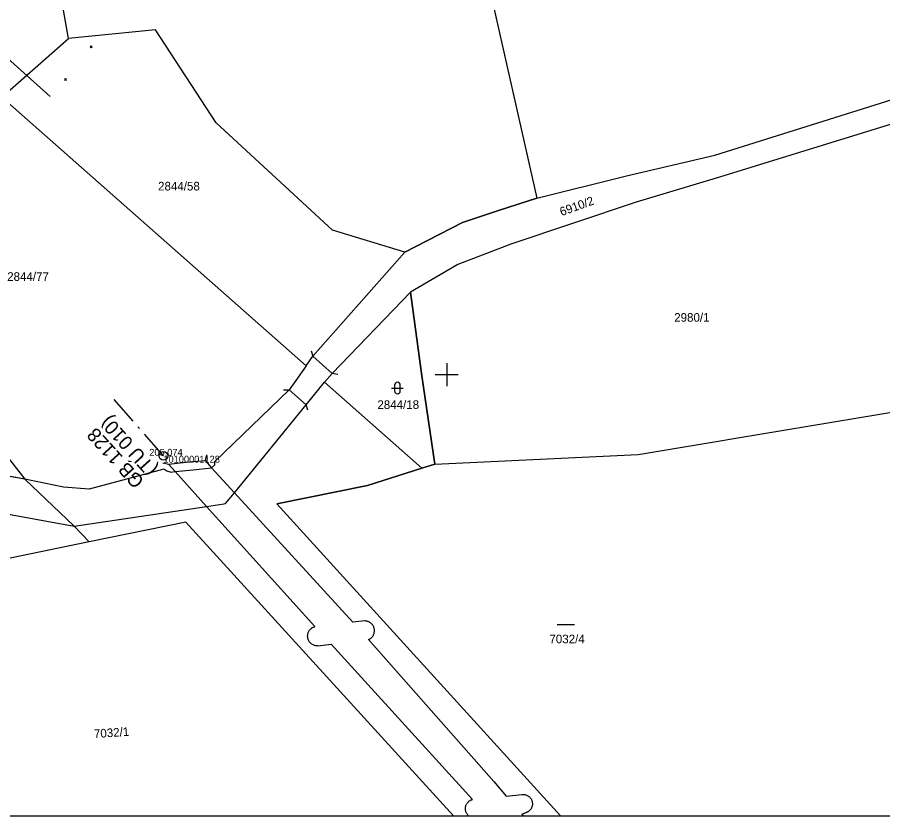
# Model space of a CAD drawing. Extents: x -800194 to -799078, y -1007177 to -1006597.
# Drawn here: x -799674.6 to -799524.3, y -1007176.6 to -1007037.9 of the extents above; entities that cross this region are included whole.
import ezdxf

# ---------------------------------------------------------------- set-up
doc = ezdxf.new("R2010")
doc.units = 0
for name, color, linetype in [('Legenda 1', 7, 'Continuous'), ('Ramove udaje', 7, 'Continuous'), ('Vrstva 49', 7, 'Continuous'), ('Vrstva 53', 7, 'Continuous'), ('Vrstva 55', 7, 'Continuous'), ('Vrstva 56', 7, 'Continuous'), ('Vrstva 57', 7, 'Continuous'), ('Vrstva 58', 7, 'Continuous'), ('Vrstva 60', 7, 'Continuous'), ('Vrstva 61', 7, 'Continuous'), ('Vrstva 63', 7, 'Continuous')]:
    doc.layers.add(name, color=color, linetype=linetype)

msp = doc.modelspace()

# ---------------------------------------------------------------- linework, layer by layer
at = {"layer": 'Legenda 1'}
msp.add_lwpolyline([(-800193.4, -1007176.65), (-799312.4, -1007176.65), (-799312.4, -1006766.65), (-800193.4, -1006766.65)], close=True, dxfattribs=at)
at = {"layer": 'Ramove udaje'}
for p, q in [((-799600, -1007098), (-799600, -1007102)), ((-799602, -1007100), (-799600, -1007100)), ((-799600, -1007100), (-799598, -1007100))]:
    msp.add_line(p, q, dxfattribs=at)
at = {"layer": 'Vrstva 49'}
for p, q in [((-799661.98, -1007042.84), (-799661.62, -1007043.19)), ((-799661.98, -1007043.19), (-799661.62, -1007042.84)), ((-799666.42, -1007048.56), (-799666.07, -1007048.91)), ((-799666.42, -1007048.91), (-799666.07, -1007048.56))]:
    msp.add_line(p, q, dxfattribs=at)
msp.add_lwpolyline([(-799716.25, -1006997.26), (-799711.44, -1007004.24), (-799711.11, -1007006.25), (-799707.44, -1007011.02), (-799702.58, -1007019.59), (-799698.24, -1007027), (-799684.87, -1007037.35), (-799668.9, -1007051.67)], dxfattribs=at)
at = {"layer": 'Vrstva 53'}
for points in [[(-799521.98, -1006977.8), (-799546.71, -1006987.83), (-799572.22, -1006995.8), (-799583.97, -1006998.26), (-799599.63, -1007001.65), (-799584.37, -1007069.36), (-799591.04, -1007071.48), (-799597.25, -1007073.58), (-799607.27, -1007078.7), (-799623.27, -1007096.82), (-799619.94, -1007099.79), (-799606.31, -1007085.7), (-799604.36, -1007100.23), (-799602.09, -1007115.59), (-799604.31, -1007116.28), (-799613.8, -1007119.26), (-799629.52, -1007122.44), (-799580.26, -1007176.65)], [(-799713.93, -1007117.37), (-799664.74, -1007126.35), (-799673.33, -1007118.14), (-799714.71, -1007110.97)], [(-799598.82, -1007176.65), (-799645.33, -1007125.63), (-799662.13, -1007129.03), (-799692.74, -1007135.4)]]:
    msp.add_lwpolyline(points, dxfattribs=at)
at = {"layer": 'Vrstva 55'}
for p, q in [((-799599.63, -1007001.65), (-799584.37, -1007069.36)), ((-799677.3, -1007051.77), (-799665.73, -1007041.59)), ((-799712.65, -1007067.97), (-799673.33, -1007118.14)), ((-799623.27, -1007096.82), (-799607.27, -1007078.7)), ((-799606.31, -1007085.7), (-799619.94, -1007099.79)), ((-799619.94, -1007099.79), (-799623.27, -1007096.82)), ((-799673.33, -1007118.14), (-799714.71, -1007110.97)), ((-799613.8, -1007119.26), (-799604.31, -1007116.28)), ((-799604.31, -1007116.28), (-799602.09, -1007115.59)), ((-799713.93, -1007117.37), (-799664.74, -1007126.35)), ((-799673.33, -1007118.14), (-799664.74, -1007126.35)), ((-799664.74, -1007126.35), (-799662.13, -1007129.03))]:
    msp.add_line(p, q, dxfattribs=at)
for points in [[(-799409.68, -1007006.29), (-799420, -1007017.54), (-799425.58, -1007022.42), (-799434.1, -1007028.26), (-799444.02, -1007032.78), (-799478.24, -1007042.75), (-799552.64, -1007065.71), (-799567.11, -1007070.01), (-799588.9, -1007077.33), (-799598.09, -1007080.87), (-799606.31, -1007085.7)], [(-799665.73, -1007041.59), (-799667.81, -1007029.7), (-799667.22, -1007009.16)], [(-799584.37, -1007069.36), (-799568.78, -1007065.44), (-799553.44, -1007061.89), (-799480.9, -1007039.1), (-799478.14, -1007038.23)], [(-799607.27, -1007078.7), (-799619.88, -1007074.91), (-799640.06, -1007056.27), (-799650.63, -1007040.08), (-799665.73, -1007041.59)], [(-799677.3, -1007051.77), (-799624.44, -1007098.49), (-799623.27, -1007096.82)], [(-799607.27, -1007078.7), (-799597.25, -1007073.58), (-799591.04, -1007071.48), (-799584.37, -1007069.36)], [(-799602.09, -1007115.59), (-799604.36, -1007100.23), (-799606.31, -1007085.7)], [(-799602.09, -1007115.59), (-799566.73, -1007113.9), (-799505.74, -1007103.69), (-799454.59, -1007096.36)], [(-799604.31, -1007116.28), (-799621.22, -1007101.34), (-799619.94, -1007099.79)], [(-799580.26, -1007176.65), (-799629.52, -1007122.44), (-799613.8, -1007119.26)], [(-799598.82, -1007176.65), (-799645.33, -1007125.63), (-799662.13, -1007129.03)], [(-799662.13, -1007129.03), (-799692.74, -1007135.4), (-799710.71, -1007144.99), (-799727.84, -1007152.76)]]:
    msp.add_lwpolyline(points, dxfattribs=at)
at = {"layer": 'Vrstva 56'}
for p, q in [((-799623.58, -1007095.87), (-799623.27, -1007096.82)), ((-799624.44, -1007098.49), (-799626.23, -1007101.04)), ((-799618.96, -1007099.98), (-799619.94, -1007099.79)), ((-799626.23, -1007101.04), (-799627.37, -1007102.67)), ((-799624.45, -1007105.23), (-799621.22, -1007101.34)), ((-799640.29, -1007115.09), (-799627.37, -1007102.67)), ((-799628.37, -1007102.62), (-799627.37, -1007102.67)), ((-799627.37, -1007102.67), (-799624.45, -1007105.23)), ((-799636.89, -1007120.54), (-799624.45, -1007105.23)), ((-799624.14, -1007106.18), (-799624.45, -1007105.23)), ((-799649.34, -1007115.32), (-799648.37, -1007115.55)), ((-799648.37, -1007115.55), (-799645.26, -1007115.24)), ((-799645.26, -1007115.24), (-799641.97, -1007114.92)), ((-799641.73, -1007113.95), (-799641.97, -1007114.92)), ((-799641.97, -1007114.92), (-799640.86, -1007116.19)), ((-799640.3, -1007115.68), (-799640.29, -1007115.09)), ((-799649.14, -1007116.42), (-799662.13, -1007119.88)), ((-799648.66, -1007116.78), (-799649.14, -1007116.42)), ((-799647.98, -1007116.94), (-799648.66, -1007116.78)), ((-799648.37, -1007115.55), (-799647.19, -1007116.86)), ((-799647.98, -1007116.94), (-799647.19, -1007116.86)), ((-799647.19, -1007116.86), (-799644.09, -1007116.53)), ((-799647.19, -1007116.86), (-799641.73, -1007122.91)), ((-799644.09, -1007116.53), (-799640.86, -1007116.19)), ((-799640.86, -1007116.19), (-799640.3, -1007115.68)), ((-799636.89, -1007120.54), (-799640.86, -1007116.19)), ((-799666.59, -1007119.58), (-799673.33, -1007118.14)), ((-799662.13, -1007119.88), (-799666.59, -1007119.58)), ((-799638.42, -1007122.42), (-799636.89, -1007120.54)), ((-799616.33, -1007143.04), (-799636.89, -1007120.54)), ((-799641.73, -1007122.91), (-799638.71, -1007122.46)), ((-799638.71, -1007122.46), (-799638.42, -1007122.42)), ((-799664.74, -1007126.35), (-799641.73, -1007122.91)), ((-799641.73, -1007122.91), (-799622.9, -1007143.79)), ((-799614.21, -1007142.8), (-799616.33, -1007143.04)), ((-799622.43, -1007147.14), (-799620.11, -1007146.85)), ((-799620.11, -1007146.85), (-799595.55, -1007173.85)), ((-799613.58, -1007146.05), (-799591.84, -1007170.73)), ((-799591.84, -1007170.73), (-799589.67, -1007173.25)), ((-799589.67, -1007173.25), (-799586.91, -1007172.97)), ((-799586.99, -1007176.37), (-799586.23, -1007176.11)), ((-799586.99, -1007176.37), (-799586.72, -1007176.65))]:
    msp.add_line(p, q, dxfattribs=at)
for points in [[(-799622.43, -1007147.14), (-799622.55, -1007147.14), (-799622.66, -1007147.13), (-799622.78, -1007147.11), (-799622.89, -1007147.09), (-799623, -1007147.06), (-799623.11, -1007147.02), (-799623.21, -1007146.97), (-799623.32, -1007146.92), (-799623.42, -1007146.86), (-799623.51, -1007146.79), (-799623.6, -1007146.72), (-799623.68, -1007146.64), (-799623.76, -1007146.56), (-799623.83, -1007146.47), (-799623.9, -1007146.37), (-799623.96, -1007146.27), (-799624.01, -1007146.17), (-799624.06, -1007146.07), (-799624.1, -1007145.96), (-799624.13, -1007145.84), (-799624.15, -1007145.73), (-799624.17, -1007145.62), (-799624.18, -1007145.5), (-799624.18, -1007145.39), (-799624.17, -1007145.27), (-799624.16, -1007145.16), (-799624.13, -1007145.04), (-799624.1, -1007144.93), (-799624.07, -1007144.82), (-799624.02, -1007144.72), (-799623.97, -1007144.61), (-799623.91, -1007144.52), (-799623.84, -1007144.42), (-799623.77, -1007144.33), (-799623.69, -1007144.24), (-799623.61, -1007144.17), (-799623.52, -1007144.09), (-799623.43, -1007144.03), (-799623.33, -1007143.96), (-799623.22, -1007143.91), (-799623.12, -1007143.86), (-799623.01, -1007143.82), (-799622.9, -1007143.79)], [(-799613.58, -1007146.05), (-799613.48, -1007146), (-799613.38, -1007145.94), (-799613.28, -1007145.88), (-799613.19, -1007145.81), (-799613.11, -1007145.74), (-799613.03, -1007145.66), (-799612.95, -1007145.57), (-799612.88, -1007145.48), (-799612.82, -1007145.38), (-799612.76, -1007145.28), (-799612.71, -1007145.18), (-799612.67, -1007145.07), (-799612.64, -1007144.97), (-799612.61, -1007144.85), (-799612.59, -1007144.74), (-799612.58, -1007144.63), (-799612.57, -1007144.52), (-799612.57, -1007144.4), (-799612.58, -1007144.29), (-799612.6, -1007144.17), (-799612.63, -1007144.06), (-799612.66, -1007143.95), (-799612.7, -1007143.85), (-799612.75, -1007143.74), (-799612.8, -1007143.64), (-799612.86, -1007143.55), (-799612.93, -1007143.45), (-799613, -1007143.36), (-799613.08, -1007143.28), (-799613.17, -1007143.21), (-799613.25, -1007143.14), (-799613.35, -1007143.07), (-799613.45, -1007143.01), (-799613.55, -1007142.96), (-799613.65, -1007142.91), (-799613.76, -1007142.88), (-799613.87, -1007142.85), (-799613.98, -1007142.82), (-799614.1, -1007142.81), (-799614.21, -1007142.8)], [(-799596.25, -1007176.65), (-799596.26, -1007176.64), (-799596.34, -1007176.56), (-799596.41, -1007176.47), (-799596.48, -1007176.38), (-799596.54, -1007176.29), (-799596.59, -1007176.19), (-799596.64, -1007176.09), (-799596.68, -1007175.98), (-799596.71, -1007175.87), (-799596.74, -1007175.76), (-799596.76, -1007175.65), (-799596.77, -1007175.54), (-799596.77, -1007175.43), (-799596.76, -1007175.32), (-799596.75, -1007175.2), (-799596.73, -1007175.09), (-799596.7, -1007174.98), (-799596.67, -1007174.88), (-799596.63, -1007174.77), (-799596.58, -1007174.67), (-799596.52, -1007174.57), (-799596.46, -1007174.48), (-799596.39, -1007174.39), (-799596.31, -1007174.31), (-799596.23, -1007174.23), (-799596.15, -1007174.15), (-799596.06, -1007174.09), (-799595.96, -1007174.03), (-799595.86, -1007173.97), (-799595.76, -1007173.92), (-799595.66, -1007173.88), (-799595.55, -1007173.85)], [(-799586.91, -1007172.97), (-799586.8, -1007172.96), (-799586.69, -1007172.96), (-799586.57, -1007172.97), (-799586.46, -1007172.98), (-799586.35, -1007173.01), (-799586.24, -1007173.04), (-799586.14, -1007173.08), (-799586.03, -1007173.12), (-799585.93, -1007173.17), (-799585.84, -1007173.23), (-799585.74, -1007173.3), (-799585.66, -1007173.37), (-799585.58, -1007173.45), (-799585.5, -1007173.53), (-799585.43, -1007173.62), (-799585.37, -1007173.71), (-799585.31, -1007173.81), (-799585.26, -1007173.91), (-799585.22, -1007174.02), (-799585.18, -1007174.12), (-799585.16, -1007174.23), (-799585.14, -1007174.34), (-799585.12, -1007174.46), (-799585.12, -1007174.57), (-799585.12, -1007174.68), (-799585.13, -1007174.79), (-799585.15, -1007174.91), (-799585.18, -1007175.02), (-799585.21, -1007175.12), (-799585.26, -1007175.23), (-799585.31, -1007175.33), (-799585.36, -1007175.43), (-799585.42, -1007175.52), (-799585.49, -1007175.61), (-799585.57, -1007175.69), (-799585.65, -1007175.77), (-799585.73, -1007175.84), (-799585.83, -1007175.91), (-799585.92, -1007175.97), (-799586.02, -1007176.03), (-799586.12, -1007176.07), (-799586.23, -1007176.11)]]:
    msp.add_lwpolyline(points, dxfattribs=at)
at = {"layer": 'Vrstva 58'}
for p, q in [((-799609.08, -1007101.83), (-799609.08, -1007102.84)), ((-799608.08, -1007102.84), (-799608.08, -1007101.83)), ((-799609.58, -1007102.33), (-799607.58, -1007102.33)), ((-799580.84, -1007143.4), (-799577.84, -1007143.4))]:
    msp.add_line(p, q, dxfattribs=at)
for centre, start, end in [((-799608.58, -1007101.83), 0, 180), ((-799608.58, -1007102.83), 180, 359.9879)]:
    msp.add_arc(centre, 0.5, start, end, dxfattribs=at)
at = {"layer": 'Vrstva 60'}
msp.add_line((-799649.24, -1007114.1), (-799649.24, -1007114.1), dxfattribs=at)
at = {"layer": 'Vrstva 63'}
for p, q in [((-799654.5, -1007108.07), (-799657.79, -1007104.31)), ((-799653.38, -1007109.35), (-799653.65, -1007109.05)), ((-799649.24, -1007114.1), (-799652.53, -1007110.33)), ((-799649.21, -1007114.13), (-799649.27, -1007114.06))]:
    msp.add_line(p, q, dxfattribs=at)
msp.add_circle((-799649.24, -1007114.1), 0.756, dxfattribs=at)

# ---------------------------------------------------------------- texts
at = {"layer": 'Vrstva 57'}
for s, p in [('2844/58', (-799650.16, -1007068)), ('2844/77', (-799676.38, -1007083.71)), ('2980/1', (-799560.49, -1007090.81)), ('2844/18', (-799612.06, -1007105.97)), ('7032/4', (-799582.17, -1007146.69))]:
    msp.add_text(s, height=1.5, dxfattribs=at).set_placement(p)
for s, rotation, p in [('6910/2', 20, (-799580.05, -1007072.47)), ('7032/1', 4, (-799661.25, -1007163.18))]:
    msp.add_text(s, height=1.5, rotation=rotation, dxfattribs=at).set_placement(p)
at = {"layer": 'Vrstva 60'}
msp.add_text('10100001128', height=1.2, dxfattribs=at).set_placement((-799649.24, -1007115.3))
at = {"layer": 'Vrstva 61'}
msp.add_text('205.074', height=1.2, dxfattribs=at).set_placement((-799651.69, -1007114.1))
at = {"layer": 'Vrstva 63'}
for s, p in [('(TÚ 010)', (-799650.14, -1007116.32)), ('GB 1128', (-799652.44, -1007118.41))]:
    msp.add_text(s, height=2.4, rotation=132.2013, dxfattribs=at).set_placement(p)

doc.saveas('drawing.dxf')
